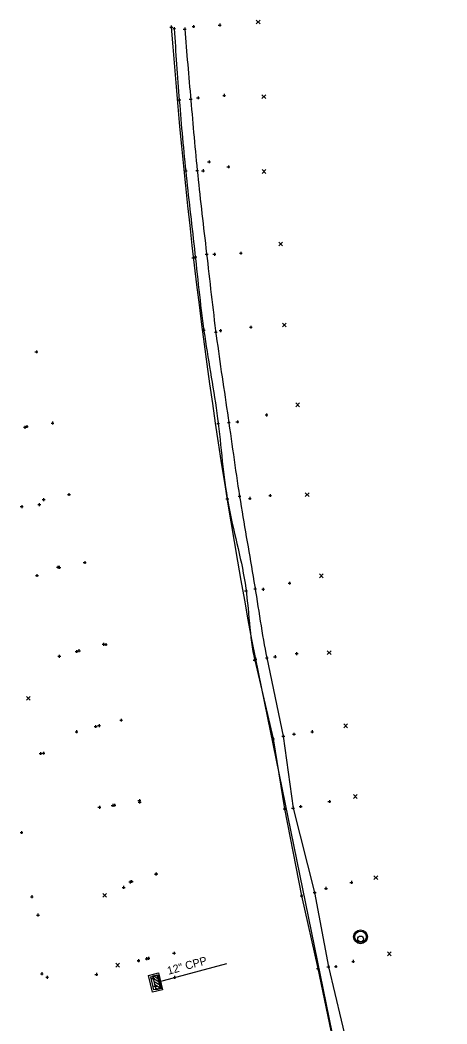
# Model space of a CAD drawing. Extents: x 2188719 to 2189819, y 654569 to 659504.
# Drawn here: x 2189566.7 to 2189715.9, y 658615.7 to 658966.8 of the extents above; entities that cross this region are included whole.
import ezdxf

# ---------------------------------------------------------------- set-up
doc = ezdxf.new("R2010")
doc.units = 0
for name, color, linetype in [('DR_X_Cells', 7, 'Continuous'), ('DR_X_Elev_Flow', 7, 'Continuous'), ('DR_X_Storm_Sewer', 7, 'Continuous'), ('DR_X_Text', 7, 'Continuous'), ('GK_Drainage_Nodes', 7, 'Continuous'), ('PM_X_Edge_Line', 7, 'Continuous'), ('PV_X_EOP', 7, 'Continuous'), ('PV_X_Shoulder', 7, 'Continuous'), ('SV_X_Random_Point', 7, 'Continuous'), ('SV_X_Shot_Marker', 7, 'Continuous')]:
    doc.layers.add(name, color=color, linetype=linetype)

msp = doc.modelspace()

# ---------------------------------------------------------------- linework, layer by layer
at = {"layer": 'DR_X_Cells'}
for p, q in [((2189615.25, 658631.31), (2189613.21, 658632.55)), ((2189615.52, 658630.21), (2189613.31, 658631.55)), ((2189614.99, 658632.41), (2189614.31, 658632.81)), ((2189615.79, 658629.11), (2189613.57, 658630.46)), ((2189615.96, 658628.07), (2189613.84, 658629.36)), ((2189614.86, 658627.8), (2189614.11, 658628.26))]:
    msp.add_line(p, q, dxfattribs=at)
for points in [[(2189613, 658626.79), (2189611.57, 658632.71), (2189615.05, 658633.55), (2189616.49, 658627.64)], [(2189613.49, 658627.6), (2189612.37, 658632.21), (2189614.56, 658632.75), (2189615.68, 658628.13)], [(2189614.25, 658627.65), (2189613.07, 658632.51), (2189614.85, 658632.95), (2189616.03, 658628.09)]]:
    msp.add_lwpolyline(points, close=True, dxfattribs=at)
for centre, radius in [((2189685.74, 658646.21), 2.42), ((2189685.74, 658646.21), 2), ((2189685.74, 658645.46), 1)]:
    msp.add_circle(centre, radius, dxfattribs=at)
at = {"layer": 'DR_X_Elev_Flow'}
for p, q in [((2189620.18, 658631.99), (2189621.18, 658631.99)), ((2189620.68, 658632.49), (2189620.68, 658631.49)), ((2189620.68, 658631.99), (2189620.68, 658631.99))]:
    msp.add_line(p, q, dxfattribs=at)
at = {"layer": 'DR_X_Storm_Sewer'}
msp.add_line((2189615.1, 658630.49), (2189638.96, 658636.88), dxfattribs=at)
at = {"layer": 'GK_Drainage_Nodes'}
for p, q in [((2189685.74, 658648.21), (2189685.74, 658648.21)), ((2189685.74, 658646.21), (2189685.74, 658646.21)), ((2189685.74, 658646.21), (2189685.74, 658646.21)), ((2189685.74, 658645.46), (2189685.74, 658645.46)), ((2189685.74, 658644.21), (2189685.74, 658644.21)), ((2189613.47, 658632.48), (2189613.47, 658632.48)), ((2189612.29, 658629.75), (2189612.29, 658629.75)), ((2189612.93, 658629.91), (2189612.93, 658629.91)), ((2189613.66, 658630.08), (2189613.66, 658630.08)), ((2189613.66, 658630.08), (2189613.66, 658630.08)), ((2189614.03, 658630.17), (2189614.03, 658630.17)), ((2189614.59, 658627.86), (2189614.59, 658627.86)), ((2189615.12, 658630.44), (2189615.12, 658630.44)), ((2189615.77, 658630.6), (2189615.77, 658630.6))]:
    msp.add_line(p, q, dxfattribs=at)
msp.add_circle((2189685.74, 658646.21), 2, dxfattribs=at)
at = {"layer": 'PM_X_Edge_Line'}
msp.add_line((2189648.95, 658743.34), (2189715.92, 658416.15), dxfattribs=at)
msp.add_arc((2191550.87, 659108.86), 1936.73, 184.27959, 190.87951, dxfattribs=at)
at = {"layer": 'PV_X_EOP'}
for p, q in [((2189648.73, 658742.97), (2189655.19, 658715.38)), ((2189655.19, 658715.38), (2189659.17, 658690.94)), ((2189659.17, 658690.94), (2189665.08, 658660.56)), ((2189665.08, 658660.56), (2189670.77, 658635.16)), ((2189670.77, 658635.16), (2189677.31, 658603.82))]:
    msp.add_line(p, q, dxfattribs=at)
msp.add_open_spline([(2189620.58, 658963.79), (2189621.09, 658955.5), (2189622.28, 658938.9), (2189624.62, 658912.29), (2189627.89, 658885.48), (2189630.83, 658855.94), (2189636.29, 658827.97), (2189638.39, 658797.14), (2189646.66, 658770.21), (2189646.87, 658750.91), (2189648.73, 658742.97)], degree=3, dxfattribs=at)
at = {"layer": 'PV_X_Shoulder'}
for p, q in [((2189652.97, 658743.7), (2189658.73, 658716.32)), ((2189658.73, 658716.32), (2189662.12, 658691.21)), ((2189662.12, 658691.21), (2189669.66, 658661.67)), ((2189669.66, 658661.67), (2189674.48, 658635.74)), ((2189674.48, 658635.74), (2189681.84, 658604.69))]:
    msp.add_line(p, q, dxfattribs=at)
msp.add_open_spline([(2189624.24, 658963.63), (2189624.93, 658955.45), (2189626.38, 658938.96), (2189628.62, 658912.7), (2189631.88, 658885.58), (2189635.11, 658856.14), (2189639.49, 658827.97), (2189643.52, 658797.98), (2189648.68, 658770.66), (2189651.28, 658751.71), (2189652.97, 658743.7)], degree=3, dxfattribs=at)
at = {"layer": 'SV_X_Random_Point'}
for p, q in [((2189649.28, 658965.45), (2189650.62, 658966.78)), ((2189649.28, 658966.78), (2189650.62, 658965.45)), ((2189651.26, 658939.33), (2189652.59, 658940.66)), ((2189651.26, 658940.66), (2189652.59, 658939.33)), ((2189651.29, 658913.16), (2189652.62, 658914.49)), ((2189651.29, 658914.49), (2189652.62, 658913.16)), ((2189657.16, 658887.83), (2189658.49, 658889.17)), ((2189657.16, 658889.17), (2189658.49, 658887.83)), ((2189658.42, 658859.46), (2189659.75, 658860.79)), ((2189658.42, 658860.79), (2189659.75, 658859.46)), ((2189663.11, 658831.57), (2189664.44, 658832.91)), ((2189663.11, 658832.91), (2189664.44, 658831.57)), ((2189666.4, 658800.15), (2189667.74, 658801.49)), ((2189666.4, 658801.49), (2189667.74, 658800.15)), ((2189671.32, 658771.75), (2189672.65, 658773.08)), ((2189671.32, 658773.08), (2189672.65, 658771.75)), ((2189674.06, 658744.88), (2189675.4, 658746.22)), ((2189674.06, 658746.22), (2189675.4, 658744.88)), ((2189568.9, 658728.91), (2189570.23, 658730.25)), ((2189568.9, 658730.25), (2189570.23, 658728.91)), ((2189679.87, 658719.31), (2189681.21, 658720.65)), ((2189679.87, 658720.65), (2189681.21, 658719.31)), ((2189683.21, 658694.59), (2189684.54, 658695.93)), ((2189683.21, 658695.93), (2189684.54, 658694.59)), ((2189690.42, 658666.18), (2189691.76, 658667.51)), ((2189690.42, 658667.51), (2189691.76, 658666.18)), ((2189595.62, 658660.04), (2189596.95, 658661.37)), ((2189595.62, 658661.37), (2189596.95, 658660.04)), ((2189695.13, 658639.56), (2189696.46, 658640.9)), ((2189695.13, 658640.9), (2189696.46, 658639.56)), ((2189600.16, 658635.59), (2189601.49, 658636.92)), ((2189600.16, 658636.92), (2189601.49, 658635.59))]:
    msp.add_line(p, q, dxfattribs=at)
at = {"layer": 'SV_X_Shot_Marker'}
for p, q in [((2189619.05, 658964.34), (2189620.05, 658964.34)), ((2189619.05, 658964.34), (2189620.05, 658964.34)), ((2189619.55, 658964.84), (2189619.55, 658963.84)), ((2189619.55, 658964.84), (2189619.55, 658963.84)), ((2189619.55, 658964.34), (2189619.55, 658964.34)), ((2189619.55, 658964.34), (2189619.55, 658964.34)), ((2189620.58, 658964.29), (2189620.58, 658963.29)), ((2189620.58, 658964.29), (2189620.58, 658963.29)), ((2189626.81, 658964.53), (2189627.81, 658964.53)), ((2189627.31, 658965.03), (2189627.31, 658964.03)), ((2189627.31, 658964.53), (2189627.31, 658964.53)), ((2189636, 658965.06), (2189637, 658965.06)), ((2189636.5, 658965.56), (2189636.5, 658964.56)), ((2189636.5, 658965.06), (2189636.5, 658965.06)), ((2189620.08, 658963.79), (2189621.08, 658963.79)), ((2189620.08, 658963.79), (2189621.08, 658963.79)), ((2189620.58, 658963.79), (2189620.58, 658963.79)), ((2189620.58, 658963.79), (2189620.58, 658963.79)), ((2189623.74, 658963.63), (2189624.74, 658963.63)), ((2189623.74, 658963.63), (2189624.74, 658963.63)), ((2189624.24, 658964.13), (2189624.24, 658963.13)), ((2189624.24, 658964.13), (2189624.24, 658963.13)), ((2189624.24, 658963.63), (2189624.24, 658963.63)), ((2189624.24, 658963.63), (2189624.24, 658963.63)), ((2189626.35, 658939.58), (2189626.35, 658938.58)), ((2189628.43, 658939.61), (2189629.43, 658939.61)), ((2189628.93, 658940.11), (2189628.93, 658939.11)), ((2189628.93, 658939.61), (2189628.93, 658939.61)), ((2189637.54, 658940.46), (2189638.54, 658940.46)), ((2189638.04, 658940.96), (2189638.04, 658939.96)), ((2189638.04, 658940.46), (2189638.04, 658940.46)), ((2189621.84, 658938.94), (2189622.84, 658938.94)), ((2189622.34, 658939.44), (2189622.34, 658938.44)), ((2189622.34, 658938.94), (2189622.34, 658938.94)), ((2189625.85, 658939.08), (2189626.85, 658939.08)), ((2189626.35, 658939.08), (2189626.35, 658939.08)), ((2189632.26, 658917.2), (2189633.26, 658917.2)), ((2189632.76, 658917.7), (2189632.76, 658916.7)), ((2189632.76, 658917.2), (2189632.76, 658917.2)), ((2189639.02, 658915.46), (2189640.02, 658915.46)), ((2189639.52, 658915.96), (2189639.52, 658914.96)), ((2189639.52, 658915.46), (2189639.52, 658915.46)), ((2189624.1, 658914.02), (2189625.1, 658914.02)), ((2189624.6, 658914.52), (2189624.6, 658913.52)), ((2189624.6, 658914.02), (2189624.6, 658914.02)), ((2189628.13, 658914.17), (2189629.13, 658914.17)), ((2189628.63, 658914.67), (2189628.63, 658913.67)), ((2189628.63, 658914.17), (2189628.63, 658914.17)), ((2189630.16, 658914.12), (2189631.16, 658914.12)), ((2189630.66, 658914.62), (2189630.66, 658913.62)), ((2189630.66, 658914.12), (2189630.66, 658914.12)), ((2189626.79, 658883.65), (2189627.79, 658883.65)), ((2189627.29, 658884.15), (2189627.29, 658883.15)), ((2189627.29, 658883.65), (2189627.29, 658883.65)), ((2189627.45, 658884.02), (2189628.45, 658884.02)), ((2189627.95, 658884.52), (2189627.95, 658883.52)), ((2189627.95, 658884.02), (2189627.95, 658884.02)), ((2189631.4, 658884.94), (2189632.4, 658884.94)), ((2189631.9, 658885.44), (2189631.9, 658884.44)), ((2189631.9, 658884.94), (2189631.9, 658884.94)), ((2189634.12, 658884.88), (2189635.12, 658884.88)), ((2189634.62, 658885.38), (2189634.62, 658884.38)), ((2189634.62, 658884.88), (2189634.62, 658884.88)), ((2189643.39, 658885.28), (2189644.39, 658885.28)), ((2189643.89, 658885.78), (2189643.89, 658884.78)), ((2189643.89, 658885.28), (2189643.89, 658885.28)), ((2189630.94, 658858.88), (2189630.94, 658857.88)), ((2189646.85, 658859.41), (2189647.85, 658859.41)), ((2189647.35, 658859.91), (2189647.35, 658858.91)), ((2189647.35, 658859.41), (2189647.35, 658859.41)), ((2189630.44, 658858.38), (2189631.44, 658858.38)), ((2189630.94, 658858.38), (2189630.94, 658858.38)), ((2189634.63, 658857.63), (2189635.63, 658857.63)), ((2189635.13, 658858.13), (2189635.13, 658857.13)), ((2189635.13, 658857.63), (2189635.13, 658857.63)), ((2189636.26, 658858.2), (2189637.26, 658858.2)), ((2189636.76, 658858.7), (2189636.76, 658857.7)), ((2189636.76, 658858.2), (2189636.76, 658858.2)), ((2189571.89, 658850.77), (2189572.89, 658850.77)), ((2189572.39, 658851.27), (2189572.39, 658850.27)), ((2189572.39, 658850.77), (2189572.39, 658850.77)), ((2189652.33, 658828.7), (2189653.33, 658828.7)), ((2189652.83, 658829.2), (2189652.83, 658828.2)), ((2189652.83, 658828.7), (2189652.83, 658828.7)), ((2189567.91, 658824.37), (2189568.91, 658824.37)), ((2189568.41, 658824.87), (2189568.41, 658823.87)), ((2189568.41, 658824.37), (2189568.41, 658824.37)), ((2189568.5, 658824.66), (2189569.5, 658824.66)), ((2189569, 658825.16), (2189569, 658824.16)), ((2189569, 658824.66), (2189569, 658824.66)), ((2189577.54, 658825.85), (2189578.54, 658825.85)), ((2189578.04, 658826.35), (2189578.04, 658825.35)), ((2189578.04, 658825.85), (2189578.04, 658825.85)), ((2189635.45, 658825.74), (2189636.45, 658825.74)), ((2189635.95, 658826.24), (2189635.95, 658825.24)), ((2189635.95, 658825.74), (2189635.95, 658825.74)), ((2189639.17, 658826.01), (2189640.17, 658826.01)), ((2189639.67, 658826.51), (2189639.67, 658825.51)), ((2189639.67, 658826.01), (2189639.67, 658826.01)), ((2189642.16, 658826.28), (2189643.16, 658826.28)), ((2189642.66, 658826.78), (2189642.66, 658825.78)), ((2189642.66, 658826.28), (2189642.66, 658826.28)), ((2189574.94, 658799.6), (2189574.94, 658798.6)), ((2189583.29, 658800.87), (2189584.29, 658800.87)), ((2189583.79, 658801.37), (2189583.79, 658800.37)), ((2189583.79, 658800.87), (2189583.79, 658800.87)), ((2189638.65, 658799.39), (2189639.65, 658799.39)), ((2189639.15, 658799.89), (2189639.15, 658798.89)), ((2189639.15, 658799.39), (2189639.15, 658799.39)), ((2189642.92, 658800.24), (2189643.92, 658800.24)), ((2189643.42, 658800.74), (2189643.42, 658799.74)), ((2189643.42, 658800.24), (2189643.42, 658800.24)), ((2189646.52, 658799.5), (2189647.52, 658799.5)), ((2189647.02, 658800), (2189647.02, 658799)), ((2189647.02, 658799.5), (2189647.02, 658799.5)), ((2189653.61, 658800.54), (2189654.61, 658800.54)), ((2189654.11, 658801.04), (2189654.11, 658800.04)), ((2189654.11, 658800.54), (2189654.11, 658800.54)), ((2189566.77, 658796.65), (2189567.77, 658796.65)), ((2189567.27, 658797.15), (2189567.27, 658796.15)), ((2189567.27, 658796.65), (2189567.27, 658796.65)), ((2189572.9, 658797.33), (2189573.9, 658797.33)), ((2189573.4, 658797.83), (2189573.4, 658796.83)), ((2189573.4, 658797.33), (2189573.4, 658797.33)), ((2189574.44, 658799.1), (2189575.44, 658799.1)), ((2189574.94, 658799.1), (2189574.94, 658799.1)), ((2189579.42, 658775.45), (2189580.42, 658775.45)), ((2189579.91, 658775.4), (2189580.91, 658775.4)), ((2189579.92, 658775.95), (2189579.92, 658774.95)), ((2189579.92, 658775.45), (2189579.92, 658775.45)), ((2189580.41, 658775.9), (2189580.41, 658774.9)), ((2189580.41, 658775.4), (2189580.41, 658775.4)), ((2189588.79, 658777.08), (2189589.79, 658777.08)), ((2189589.29, 658777.58), (2189589.29, 658776.58)), ((2189589.29, 658777.08), (2189589.29, 658777.08)), ((2189572.09, 658772.56), (2189573.09, 658772.56)), ((2189572.59, 658773.06), (2189572.59, 658772.06)), ((2189572.59, 658772.56), (2189572.59, 658772.56)), ((2189645.7, 658767.71), (2189645.7, 658766.71)), ((2189648.38, 658767.91), (2189649.38, 658767.91)), ((2189648.88, 658768.41), (2189648.88, 658767.41)), ((2189648.88, 658767.91), (2189648.88, 658767.91)), ((2189651.19, 658767.73), (2189652.19, 658767.73)), ((2189651.69, 658768.23), (2189651.69, 658767.23)), ((2189651.69, 658767.73), (2189651.69, 658767.73)), ((2189660.38, 658769.89), (2189661.38, 658769.89)), ((2189660.88, 658770.39), (2189660.88, 658769.39)), ((2189660.88, 658769.89), (2189660.88, 658769.89)), ((2189645.2, 658767.21), (2189646.2, 658767.21)), ((2189645.7, 658767.21), (2189645.7, 658767.21)), ((2189587.27, 658746.74), (2189587.27, 658745.74)), ((2189595.35, 658748.48), (2189596.35, 658748.48)), ((2189595.85, 658748.98), (2189595.85, 658747.98)), ((2189595.85, 658748.48), (2189595.85, 658748.48)), ((2189596.14, 658748.4), (2189597.14, 658748.4)), ((2189596.64, 658748.9), (2189596.64, 658747.9)), ((2189596.64, 658748.4), (2189596.64, 658748.4)), ((2189579.91, 658744.3), (2189580.91, 658744.3)), ((2189580.41, 658744.8), (2189580.41, 658743.8)), ((2189580.41, 658744.3), (2189580.41, 658744.3)), ((2189585.92, 658745.95), (2189586.92, 658745.95)), ((2189586.42, 658746.45), (2189586.42, 658745.45)), ((2189586.42, 658745.95), (2189586.42, 658745.95)), ((2189586.77, 658746.24), (2189587.77, 658746.24)), ((2189587.27, 658746.24), (2189587.27, 658746.24)), ((2189648.45, 658743.34), (2189649.45, 658743.34)), ((2189648.73, 658743.47), (2189648.73, 658742.47)), ((2189648.95, 658743.84), (2189648.95, 658742.84)), ((2189648.95, 658743.34), (2189648.95, 658743.34)), ((2189652.47, 658743.7), (2189653.47, 658743.7)), ((2189652.97, 658744.2), (2189652.97, 658743.2)), ((2189652.97, 658743.7), (2189652.97, 658743.7)), ((2189655.33, 658744.13), (2189656.33, 658744.13)), ((2189655.83, 658744.63), (2189655.83, 658743.63)), ((2189655.83, 658744.13), (2189655.83, 658744.13)), ((2189662.89, 658745.24), (2189663.89, 658745.24)), ((2189663.39, 658745.74), (2189663.39, 658744.74)), ((2189663.39, 658745.24), (2189663.39, 658745.24)), ((2189648.23, 658742.97), (2189649.23, 658742.97)), ((2189648.73, 658742.97), (2189648.73, 658742.97)), ((2189601.53, 658721.96), (2189602.53, 658721.96)), ((2189602.03, 658722.46), (2189602.03, 658721.46)), ((2189602.03, 658721.96), (2189602.03, 658721.96)), ((2189586.43, 658718.42), (2189586.43, 658717.42)), ((2189592.62, 658719.75), (2189593.62, 658719.75)), ((2189593.12, 658720.25), (2189593.12, 658719.25)), ((2189593.12, 658719.75), (2189593.12, 658719.75)), ((2189593.82, 658720.05), (2189594.82, 658720.05)), ((2189594.32, 658720.55), (2189594.32, 658719.55)), ((2189594.32, 658720.05), (2189594.32, 658720.05)), ((2189585.93, 658717.92), (2189586.93, 658717.92)), ((2189586.43, 658717.92), (2189586.43, 658717.92)), ((2189654.69, 658715.38), (2189655.69, 658715.38)), ((2189655.19, 658715.88), (2189655.19, 658714.88)), ((2189655.19, 658715.38), (2189655.19, 658715.38)), ((2189658.23, 658716.32), (2189659.23, 658716.32)), ((2189658.73, 658716.82), (2189658.73, 658715.82)), ((2189658.73, 658716.32), (2189658.73, 658716.32)), ((2189661.96, 658717.08), (2189662.96, 658717.08)), ((2189662.46, 658717.58), (2189662.46, 658716.58)), ((2189662.46, 658717.08), (2189662.46, 658717.08)), ((2189668.29, 658717.92), (2189669.29, 658717.92)), ((2189668.79, 658718.42), (2189668.79, 658717.42)), ((2189668.79, 658717.92), (2189668.79, 658717.92)), ((2189573.39, 658710.29), (2189574.39, 658710.29)), ((2189573.89, 658710.79), (2189573.89, 658709.79)), ((2189573.89, 658710.29), (2189573.89, 658710.29)), ((2189574.34, 658710.4), (2189575.34, 658710.4)), ((2189574.84, 658710.9), (2189574.84, 658709.9)), ((2189574.84, 658710.4), (2189574.84, 658710.4)), ((2189607.9, 658693.87), (2189608.9, 658693.87)), ((2189608.4, 658694.37), (2189608.4, 658693.37)), ((2189608.4, 658693.87), (2189608.4, 658693.87)), ((2189674.82, 658694.03), (2189674.82, 658693.03)), ((2189593.92, 658691.48), (2189594.92, 658691.48)), ((2189594.42, 658691.98), (2189594.42, 658690.98)), ((2189594.42, 658691.48), (2189594.42, 658691.48)), ((2189598.59, 658692.15), (2189599.59, 658692.15)), ((2189599.09, 658692.65), (2189599.09, 658691.65)), ((2189599.09, 658692.15), (2189599.09, 658692.15)), ((2189599.22, 658692.22), (2189600.22, 658692.22)), ((2189599.72, 658692.72), (2189599.72, 658691.72)), ((2189599.72, 658692.22), (2189599.72, 658692.22)), ((2189608, 658693.32), (2189609, 658693.32)), ((2189608.5, 658693.82), (2189608.5, 658692.82)), ((2189608.5, 658693.32), (2189608.5, 658693.32)), ((2189658.67, 658690.94), (2189659.67, 658690.94)), ((2189659.17, 658691.44), (2189659.17, 658690.44)), ((2189659.17, 658690.94), (2189659.17, 658690.94)), ((2189661.62, 658691.21), (2189662.62, 658691.21)), ((2189662.12, 658691.71), (2189662.12, 658690.71)), ((2189662.12, 658691.21), (2189662.12, 658691.21)), ((2189664.26, 658691.74), (2189665.26, 658691.74)), ((2189664.76, 658692.24), (2189664.76, 658691.24)), ((2189664.76, 658691.74), (2189664.76, 658691.74)), ((2189674.32, 658693.53), (2189675.32, 658693.53)), ((2189674.82, 658693.53), (2189674.82, 658693.53)), ((2189566.7, 658682.68), (2189567.7, 658682.68)), ((2189567.2, 658683.18), (2189567.2, 658682.18)), ((2189567.2, 658682.68), (2189567.2, 658682.68)), ((2189605.21, 658665.88), (2189605.21, 658664.88)), ((2189605.69, 658666.04), (2189605.69, 658665.04)), ((2189613.67, 658668.12), (2189614.67, 658668.12)), ((2189613.8, 658668.23), (2189614.8, 658668.23)), ((2189614.17, 658668.62), (2189614.17, 658667.62)), ((2189614.17, 658668.12), (2189614.17, 658668.12)), ((2189614.3, 658668.73), (2189614.3, 658667.73)), ((2189614.3, 658668.23), (2189614.3, 658668.23)), ((2189602.4, 658663.49), (2189603.4, 658663.49)), ((2189602.9, 658663.99), (2189602.9, 658662.99)), ((2189602.9, 658663.49), (2189602.9, 658663.49)), ((2189604.71, 658665.38), (2189605.71, 658665.38)), ((2189605.19, 658665.54), (2189606.19, 658665.54)), ((2189605.21, 658665.38), (2189605.21, 658665.38)), ((2189605.69, 658665.54), (2189605.69, 658665.54)), ((2189673.14, 658663.13), (2189674.14, 658663.13)), ((2189673.64, 658663.63), (2189673.64, 658662.63)), ((2189673.64, 658663.13), (2189673.64, 658663.13)), ((2189682.03, 658665.23), (2189683.03, 658665.23)), ((2189682.53, 658665.73), (2189682.53, 658664.73)), ((2189682.53, 658665.23), (2189682.53, 658665.23)), ((2189570.3, 658660.22), (2189571.3, 658660.22)), ((2189570.8, 658660.72), (2189570.8, 658659.72)), ((2189570.8, 658660.22), (2189570.8, 658660.22)), ((2189664.58, 658660.56), (2189665.58, 658660.56)), ((2189665.08, 658661.06), (2189665.08, 658660.06)), ((2189665.08, 658660.56), (2189665.08, 658660.56)), ((2189669.16, 658661.67), (2189670.16, 658661.67)), ((2189669.66, 658662.17), (2189669.66, 658661.17)), ((2189669.66, 658661.67), (2189669.66, 658661.67)), ((2189572.46, 658653.82), (2189573.46, 658653.82)), ((2189572.96, 658654.32), (2189572.96, 658653.32)), ((2189572.96, 658653.82), (2189572.96, 658653.82)), ((2189607.6, 658637.86), (2189608.6, 658637.86)), ((2189607.6, 658637.84), (2189608.6, 658637.84)), ((2189608.1, 658638.36), (2189608.1, 658637.36)), ((2189608.1, 658638.34), (2189608.1, 658637.34)), ((2189608.1, 658637.86), (2189608.1, 658637.86)), ((2189608.1, 658637.84), (2189608.1, 658637.84)), ((2189610.42, 658638.52), (2189611.42, 658638.52)), ((2189610.92, 658639.02), (2189610.92, 658638.02)), ((2189610.92, 658638.52), (2189610.92, 658638.52)), ((2189611.11, 658638.7), (2189612.11, 658638.7)), ((2189611.61, 658639.2), (2189611.61, 658638.2)), ((2189611.61, 658638.7), (2189611.61, 658638.7)), ((2189620.04, 658640.49), (2189621.04, 658640.49)), ((2189620.54, 658640.99), (2189620.54, 658639.99)), ((2189620.54, 658640.49), (2189620.54, 658640.49)), ((2189683.16, 658638.1), (2189683.16, 658637.1)), ((2189670.27, 658635.16), (2189671.27, 658635.16)), ((2189670.77, 658635.66), (2189670.77, 658634.66)), ((2189670.77, 658635.16), (2189670.77, 658635.16)), ((2189673.98, 658635.74), (2189674.98, 658635.74)), ((2189674.48, 658636.24), (2189674.48, 658635.24)), ((2189674.48, 658635.74), (2189674.48, 658635.74)), ((2189676.58, 658635.83), (2189677.58, 658635.83)), ((2189677.08, 658636.33), (2189677.08, 658635.33)), ((2189677.08, 658635.83), (2189677.08, 658635.83)), ((2189682.66, 658637.6), (2189683.66, 658637.6)), ((2189683.16, 658637.6), (2189683.16, 658637.6)), ((2189573.8, 658633.29), (2189574.8, 658633.29)), ((2189574.3, 658633.79), (2189574.3, 658632.79)), ((2189574.3, 658633.29), (2189574.3, 658633.29)), ((2189575.65, 658632.05), (2189576.65, 658632.05)), ((2189576.15, 658632.55), (2189576.15, 658631.55)), ((2189576.15, 658632.05), (2189576.15, 658632.05)), ((2189592.86, 658633.06), (2189593.86, 658633.06)), ((2189593.36, 658633.56), (2189593.36, 658632.56)), ((2189593.36, 658633.06), (2189593.36, 658633.06)), ((2189612.77, 658631.65), (2189613.77, 658631.65)), ((2189613.27, 658632.15), (2189613.27, 658631.15)), ((2189613.27, 658631.65), (2189613.27, 658631.65)), ((2189613.48, 658628.91), (2189614.48, 658628.91)), ((2189613.98, 658629.41), (2189613.98, 658628.41)), ((2189613.98, 658628.91), (2189613.98, 658628.91))]:
    msp.add_line(p, q, dxfattribs=at)

# ---------------------------------------------------------------- texts
at = {"layer": 'DR_X_Text'}
msp.add_text('12" CPP', height=2.8, rotation=15.3942, dxfattribs=at).set_placement((2189618.56, 658632.9))

doc.saveas('drawing.dxf')
